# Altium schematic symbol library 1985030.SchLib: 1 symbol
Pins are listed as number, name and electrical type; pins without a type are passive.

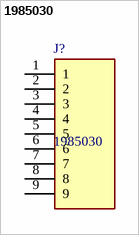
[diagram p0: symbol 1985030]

## 1985030
designator J?
PCB terminal block, nominal current: 8 A, rated voltage (III/2): 250 V, nominal cross section: 1.5 mm?, Number of potentials: 9, Number of rows: 1, Number of positions per row: 9, product range: PTSA 1,5, pitch: 3.5 mm, connection method: Push-in spring connection, mounting: Wave soldering, conductor/PCB connection direction: 45 ?, color: green, Pin layout: Linear pinning, Solder pin [P]: 3.6 mm, type of packaging: packed in cardboard. Soldering legs in front area, one-rowed; Manufacturer_Name: Phoenix Contact; Geometry.Height: 13.1mm
footprint 1985030
pins: 1, 2, 3, 4, 5, 6, 7, 8, 9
